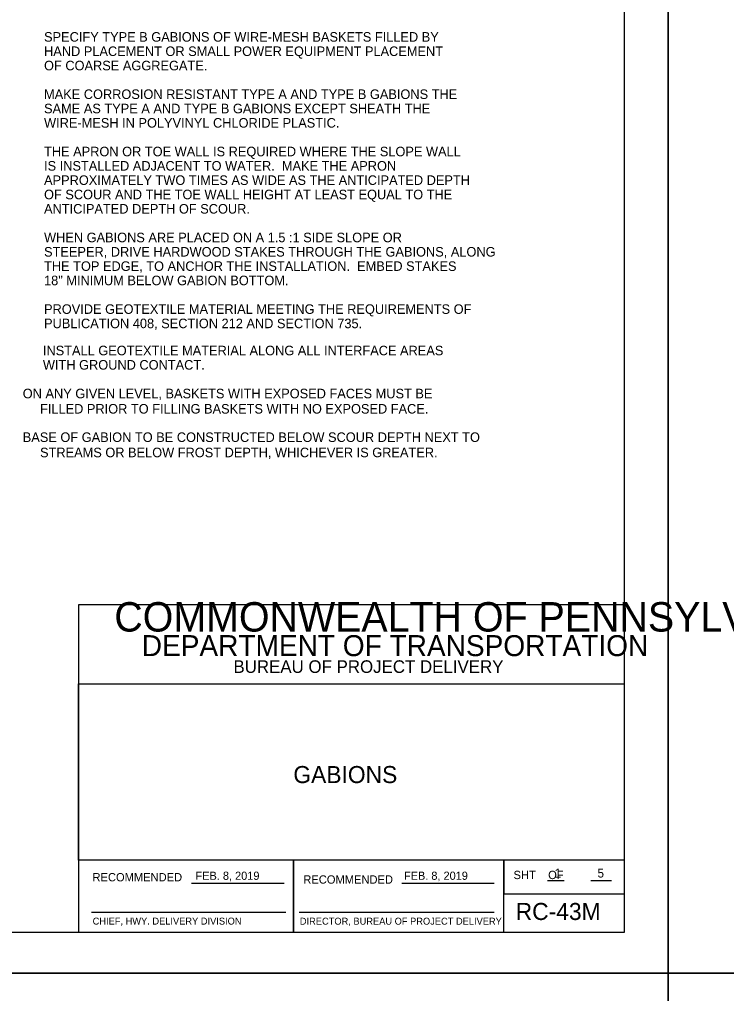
# Model space of a CAD drawing. Extents: x 3 to 3592, y -602 to 1171.
# Drawn here: x 605.9 to 864.9, y 569.3 to 926.3 of the extents above; entities that cross this region are included whole.
import ezdxf

# ---------------------------------------------------------------- set-up
doc = ezdxf.new("R2010")
doc.units = 0
for name, color, linetype in [('1', 7, 'Continuous'), ('2', 7, 'Continuous'), ('3', 7, 'Continuous'), ('40', 7, 'Continuous'), ('PLT-BNDY', 7, 'Continuous')]:
    doc.layers.add(name, color=color, linetype=linetype)

msp = doc.modelspace()

# ---------------------------------------------------------------- linework, layer by layer
at = {"layer": '1'}
for p, q in [((799.37, 610.81), (805.51, 610.81)), ((815.18, 610.81), (822.83, 610.81)), ((668.97, 609.82), (702.86, 609.82)), ((745.97, 609.82), (779.84, 609.82)), ((632.27, 599.16), (703.52, 599.16)), ((708.44, 599.16), (779.78, 599.16))]:
    msp.add_line(p, q, dxfattribs=at)
msp.add_lwpolyline([(827.51, 591.83), (827.51, 1155.83), (41.51, 1155.83), (41.51, 591.83), (827.51, 591.83), (827.51, 618.19), (627.51, 618.19), (627.51, 682.87), (827.51, 682.87), (827.51, 711.83), (627.51, 711.83), (627.51, 591.83), (706.31, 591.83), (706.31, 618.19), (706.31, 591.83), (783.31, 591.83), (783.31, 618.19), (783.31, 605.88), (827.51, 605.88)], dxfattribs=at)
at = {"layer": 'PLT-BNDY'}
for points in [[(2.51, 1170.83), (843.51, 1170.83), (843.51, 576.83), (2.51, 576.83)], [(843.51, 1170.83), (1684.51, 1170.83), (1684.51, 576.83), (843.51, 576.83)], [(2.51, 576.83), (843.51, 576.83), (843.51, -17.17), (2.51, -17.17)], [(843.51, 576.83), (1684.51, 576.83), (1684.51, -17.17), (843.51, -17.17)]]:
    msp.add_lwpolyline(points, close=True, dxfattribs=at)

# ---------------------------------------------------------------- texts
at = {"layer": '1'}
for s, height, p in [('COMMONWEALTH OF PENNSYLVANIA', 10.7834, (640.66, 701.98)), ('DEPARTMENT OF TRANSPORTATION', 7.6843, (650.72, 692.98)), ('BUREAU OF PROJECT DELIVERY', 4.6221, (684.31, 686.82)), ('GABIONS', 6.25, (706.25, 646.45)), ('FEB. 8, 2019', 3, (670.42, 611)), ('FEB. 8, 2019', 3, (746.77, 611)), ('SHT    OF', 3.048, (786.91, 611.26)), ('1', 3.25, (801.94, 611.83)), ('5', 3.25, (817.65, 611.83)), ('RECOMMENDED', 3.048, (632.67, 610.43)), ('RECOMMENDED', 3.048, (709.91, 609.59)), ('APPROVED', 0.0192, (670.53, 609.77)), ('RC-43M', 6.25, (787.7, 596.28)), ('CHIEF, HWY. DELIVERY DIVISION', 2.54, (632.73, 594.6)), ('DIRECTOR, BUREAU OF PROJECT DELIVERY', 2.54, (708.64, 594.57))]:
    msp.add_text(s, height=height, dxfattribs=at).set_placement(p)
at = {"layer": '2'}
for s, p in [('   ON ANY GIVEN LEVEL, BASKETS WITH EXPOSED FACES MUST BE', (603.23, 787.46)), ('   BASE OF GABION TO BE CONSTRUCTED BELOW SCOUR DEPTH NEXT TO', (603.23, 771.46))]:
    msp.add_text(s, height=3.5, dxfattribs=at).set_placement(p)
at = {"layer": '3'}
for s, p in [('SPECIFY TYPE B GABIONS OF WIRE-MESH BASKETS FILLED BY ', (614.93, 918.15)), ('HAND PLACEMENT OR SMALL POWER EQUIPMENT PLACEMENT', (614.93, 912.9)), ('OF COARSE AGGREGATE.', (614.93, 907.65)), ('MAKE CORROSION RESISTANT TYPE A AND TYPE B GABIONS THE', (614.93, 897.15)), ('SAME AS TYPE A AND TYPE B GABIONS EXCEPT SHEATH THE ', (614.93, 891.9)), ('WIRE-MESH IN POLYVINYL CHLORIDE PLASTIC.', (614.93, 886.65)), ('THE APRON OR TOE WALL IS REQUIRED WHERE THE SLOPE WALL', (614.93, 876.15)), ('IS INSTALLED ADJACENT TO WATER.  MAKE THE APRON', (614.93, 870.9)), ('APPROXIMATELY TWO TIMES AS WIDE AS THE ANTICIPATED DEPTH', (614.93, 865.65)), ('OF SCOUR AND THE TOE WALL HEIGHT AT LEAST EQUAL TO THE', (614.93, 860.4)), ('ANTICIPATED DEPTH OF SCOUR.', (614.93, 855.15)), ('WHEN GABIONS ARE PLACED ON A 1.5 :1 SIDE SLOPE OR', (614.93, 844.65)), ('STEEPER, DRIVE HARDWOOD STAKES THROUGH THE GABIONS, ALONG', (614.93, 839.4)), ('THE TOP EDGE, TO ANCHOR THE INSTALLATION.  EMBED STAKES', (614.93, 834.15)), ('18" MINIMUM BELOW GABION BOTTOM.', (614.93, 828.9)), ('PROVIDE GEOTEXTILE MATERIAL MEETING THE REQUIREMENTS OF', (614.93, 818.4)), ('PUBLICATION 408, SECTION 212 AND SECTION 735.', (614.93, 813.15)), ('INSTALL GEOTEXTILE MATERIAL ALONG ALL INTERFACE AREAS ', (614.51, 803.22)), ('WITH GROUND CONTACT.', (614.51, 797.97))]:
    msp.add_text(s, height=3.5, dxfattribs=at).set_placement(p)
at = {"layer": '40'}
for s, p in [('FILLED PRIOR TO FILLING BASKETS WITH NO EXPOSED FACE.', (613.46, 781.86)), ('STREAMS OR BELOW FROST DEPTH, WHICHEVER IS GREATER.', (613.46, 765.86))]:
    msp.add_text(s, height=3.5, dxfattribs=at).set_placement(p)

doc.saveas('drawing.dxf')
